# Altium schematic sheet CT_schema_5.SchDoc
size 258 x 163 mm
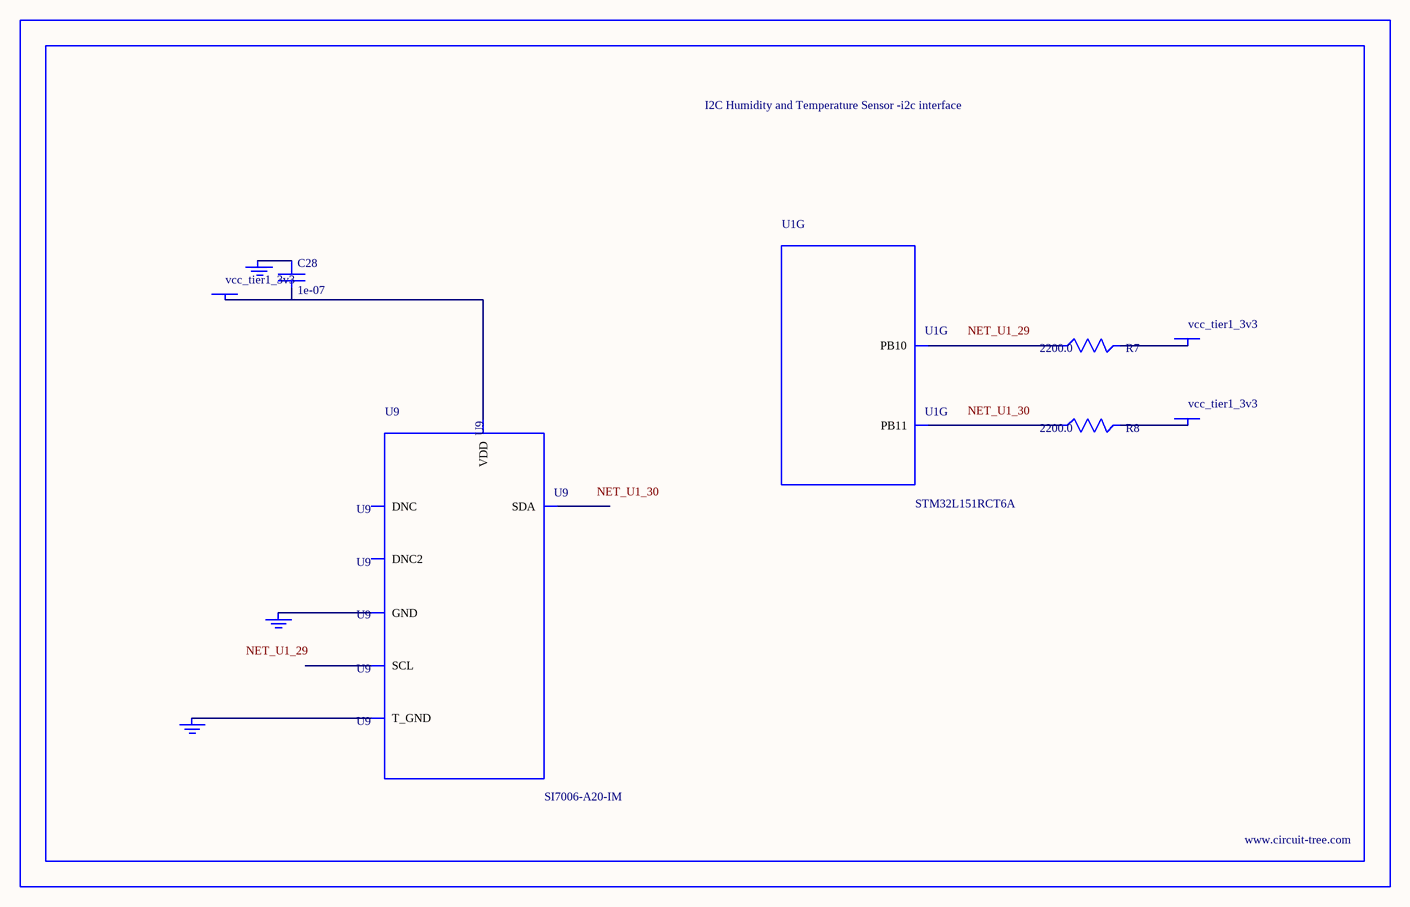
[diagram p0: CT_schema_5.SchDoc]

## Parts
BORDER4  (no value)
C28  1e-07  [C0402]
GND_INSTANCE_4_0  (no value)
GND_INSTANCE_4_1  (no value)
GND_INSTANCE_4_2  (no value)
POWER_INSTANCE_4_0  vcc_tier1_3v3
POWER_INSTANCE_4_1  vcc_tier1_3v3
POWER_INSTANCE_4_2  vcc_tier1_3v3
R7  2200.0  [R0603]
R8  2200.0  [R0603]
U1  STM32L151RCT6A  [LQFP64]  (part G of 8)
U9  SI7006-A20-IM  [DFN-6]

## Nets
NetC28_1: C28.1 GND_INSTANCE_4_0.0(GND)
NetC28_2: C28.2 POWER_INSTANCE_4_0.0(PWR) U9.5(VDD)
NetGND_INSTANCE_4_1_0: GND_INSTANCE_4_1.0(GND) U9.7(T_GND)
NetGND_INSTANCE_4_2_0: GND_INSTANCE_4_2.0(GND) U9.2(GND)
NetPOWER_INSTANCE_4_1_0: POWER_INSTANCE_4_1.0(PWR) R7.2
NetPOWER_INSTANCE_4_2_0: POWER_INSTANCE_4_2.0(PWR) R8.2
NetR7_1: R7.1 U1.29(PB10)
NetR8_1: R8.1 U1.30(PB11)

Not connected (* = marked no-connect by the designer): U9 1(SDA) 3(DNC) 4(DNC2) 6(SCL)

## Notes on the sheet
- Labels drawn without touching a wire or pin: NET_U1_29, NET_U1_30

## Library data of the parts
BORDER4 = BORDER_PAGE4
C28 = C0402C104K3RACTU
GND_INSTANCE_4_0-GND_INSTANCE_4_2 = GND
POWER_INSTANCE_4_0-POWER_INSTANCE_4_2 = PWR
R7 R8 = RC0603JR-072K2L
